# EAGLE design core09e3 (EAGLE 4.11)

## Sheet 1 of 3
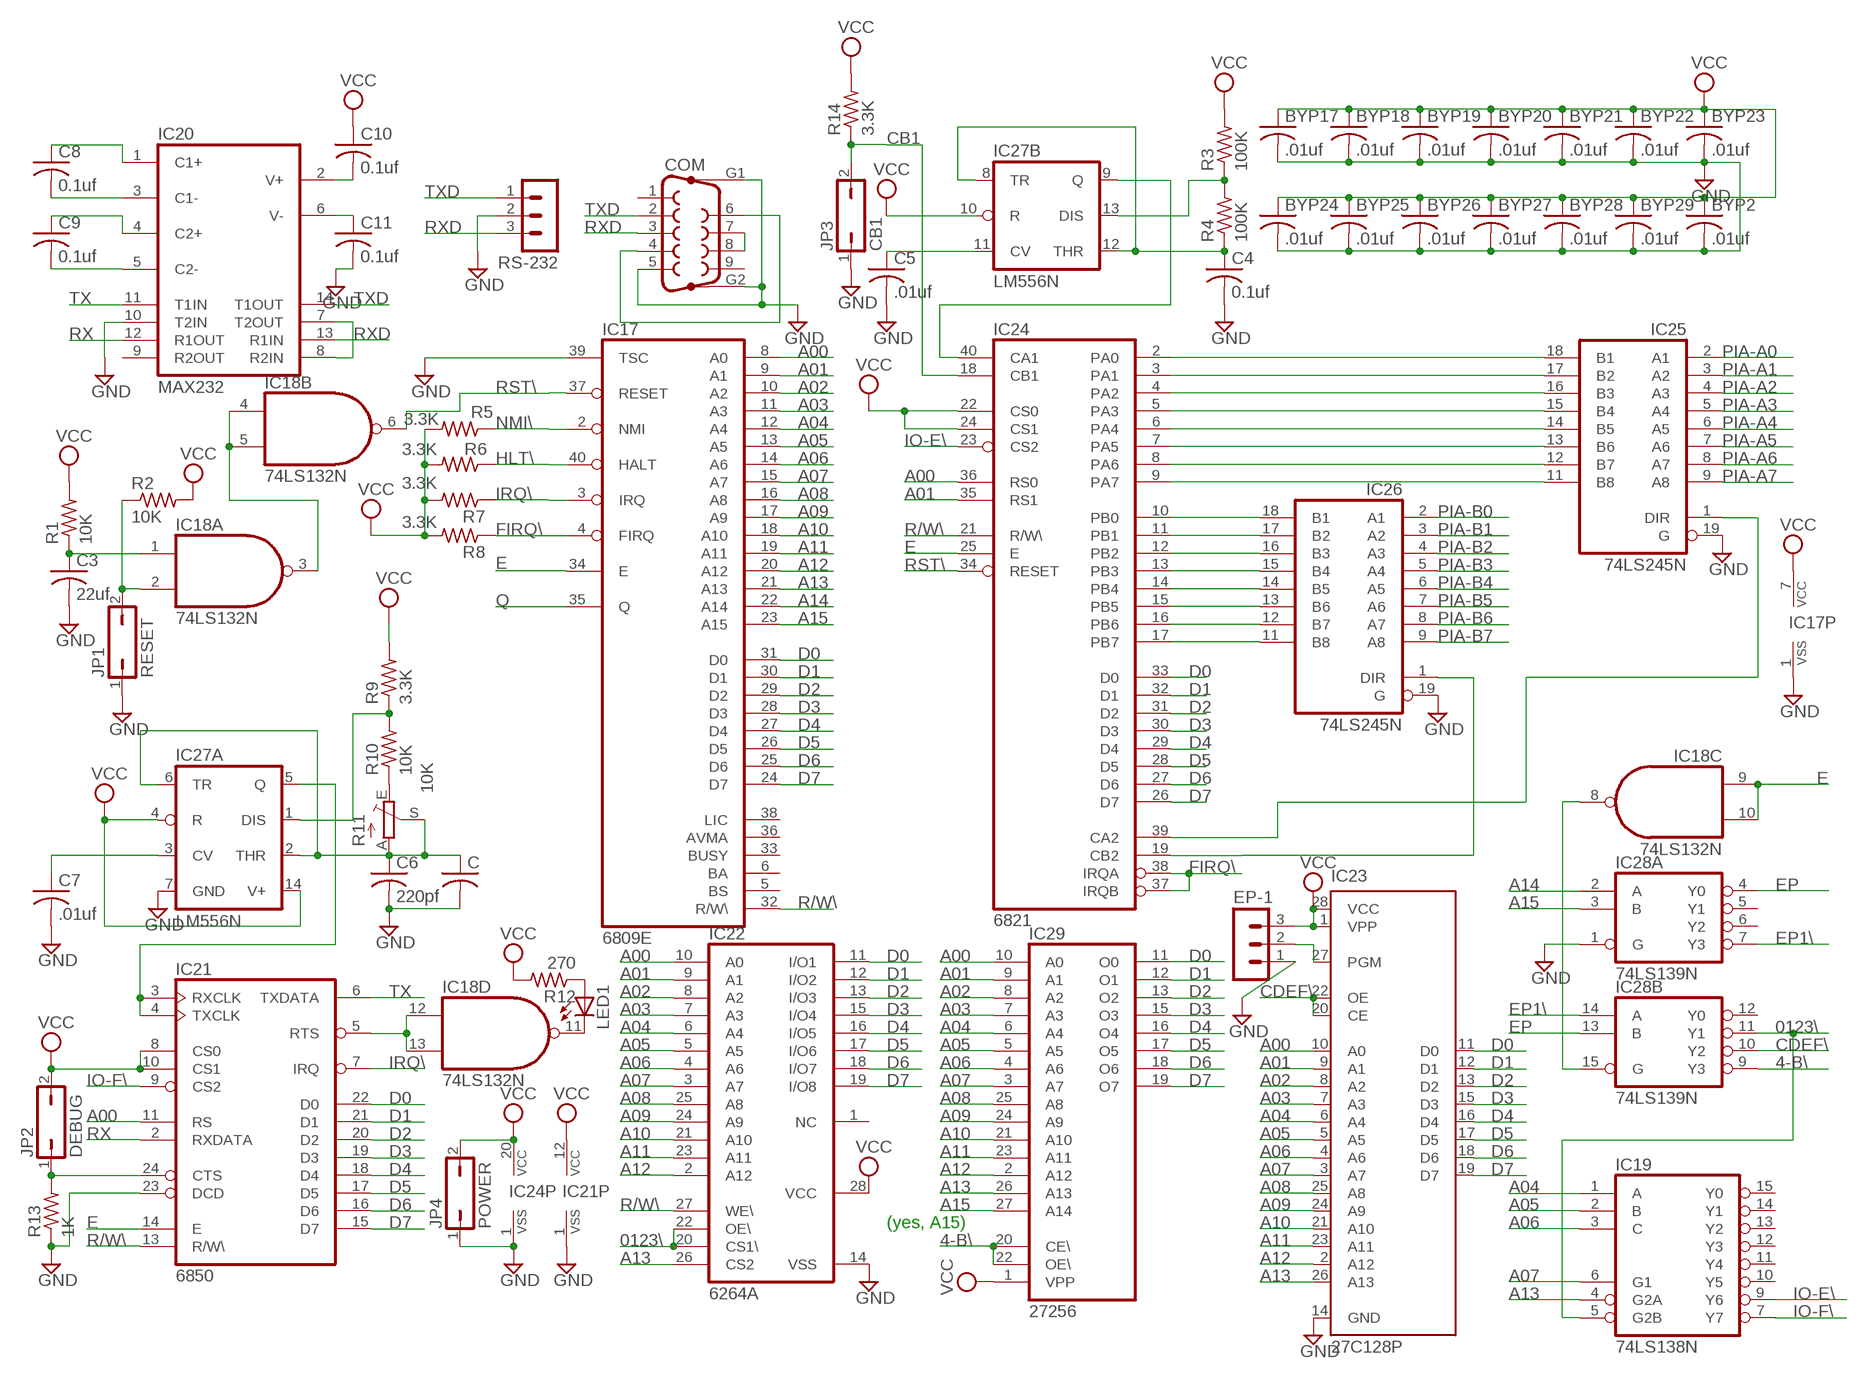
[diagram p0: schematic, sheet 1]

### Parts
BYP2  .01uf  C-US050-025X075  [C050-025X075]
BYP17  .01uf  C-US050-025X075  [C050-025X075]
BYP18  .01uf  C-US050-025X075  [C050-025X075]
BYP19  .01uf  C-US050-025X075  [C050-025X075]
BYP20  .01uf  C-US050-025X075  [C050-025X075]
BYP21  .01uf  C-US050-025X075  [C050-025X075]
BYP22  .01uf  C-US050-025X075  [C050-025X075]
BYP23  .01uf  C-US050-025X075  [C050-025X075]
BYP24  .01uf  C-US050-025X075  [C050-025X075]
BYP25  .01uf  C-US050-025X075  [C050-025X075]
BYP26  .01uf  C-US050-025X075  [C050-025X075]
BYP27  .01uf  C-US050-025X075  [C050-025X075]
BYP28  .01uf  C-US050-025X075  [C050-025X075]
BYP29  .01uf  C-US050-025X075  [C050-025X075]
C  C-US050-025X075  [C050-025X075]
C3  22uf  C-US102-054X133  [C102-054X133]
C4  0.1uf  C-US050-025X075  [C050-025X075]
C5  .01uf  C-US050-025X075  [C050-025X075]
C6  220pf  C-US050-025X075  [C050-025X075]
C7  .01uf  C-US050-025X075  [C050-025X075]
C8  0.1uf  C-US050-025X075  [C050-025X075]
C9  0.1uf  C-US050-025X075  [C050-025X075]
C10  0.1uf  C-US050-025X075  [C050-025X075]
C11  0.1uf  C-US050-025X075  [C050-025X075]
COM  F09HP  [F09HP]
EP-1  MA03-1  [MA03-1]
IC17  6809E  [DIL40]
IC18  74LS132N  74LS00N  [DIL14]
IC19  74LS138N  [DIL16]
IC20  MAX232  [DIL16]
IC21  6850  [DIL24]
IC22  6264A  [DIL28-6]
IC23  27C128P  [DIL28-6]
IC24  6821  [DIL40]
IC25  74LS245N  [DIL20]
IC26  74LS245N  [DIL20]
IC27  LM556N  [DIL14]
IC28  74LS139N  [DIL16]
IC29  27256  [DIL28]
JP1  RESET  JP1Q  [JP1]
JP2  DEBUG  JP1Q  [JP1]
JP3  CB1  JP1Q  [JP1]
JP4  POWER  JP1Q  [JP1]
LED1  LED3MM  [LED3MM]
R1  10K  R-US_0207/7  [0207/7]
R2  10K  R-US_0207/7  [0207/7]
R3  100K  R-US_0207/7  [0207/7]
R4  100K  R-US_0207/7  [0207/7]
R5  3.3K  R-US_0207/7  [0207/7]
R6  3.3K  R-US_0207/7  [0207/7]
R7  3.3K  R-US_0207/7  [0207/7]
R8  3.3K  R-US_0207/7  [0207/7]
R9  3.3K  R-US_0207/7  [0207/7]
R10  10K  R-US_0207/7  [0207/7]
R11  10K  TRIM_EU-B90P  [SP19L]
R12  270  R-US_0207/7  [0207/7]
R13  1K  R-US_0207/7  [0207/7]
R14  3.3K  R-US_0207/7  [0207/7]
RS-232  MA03-1  [MA03-1]

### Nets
4-B\: IC28.9(B:Y3) IC29.20(CE\) IC29.22(OE\)
0123\: IC19.5(G2B) IC22.20(CS1\) IC22.22(OE\) IC28.11(B:Y1)
A00: IC17.8(A0) IC21.11(RS) IC22.10(A0) IC23.10(A0) IC24.36(RS0) IC29.10(A0)
A01: IC17.9(A1) IC22.9(A1) IC23.9(A1) IC24.35(RS1) IC29.9(A1)
A02: IC17.10(A2) IC22.8(A2) IC23.8(A2) IC29.8(A2)
A03: IC17.11(A3) IC22.7(A3) IC23.7(A3) IC29.7(A3)
A04: IC17.12(A4) IC19.1(A) IC22.6(A4) IC23.6(A4) IC29.6(A4)
A05: IC17.13(A5) IC19.2(B) IC22.5(A5) IC23.5(A5) IC29.5(A5)
A06: IC17.14(A6) IC19.3(C) IC22.4(A6) IC23.4(A6) IC29.4(A6)
A07: IC17.15(A7) IC19.6(G1) IC22.3(A7) IC23.3(A7) IC29.3(A7)
A08: IC17.16(A8) IC22.25(A8) IC23.25(A8) IC29.25(A8)
A09: IC17.17(A9) IC22.24(A9) IC23.24(A9) IC29.24(A9)
A10: IC17.18(A10) IC22.21(A10) IC23.21(A10) IC29.21(A10)
A11: IC17.19(A11) IC22.23(A11) IC23.23(A11) IC29.23(A11)
A12: IC17.20(A12) IC22.2(A12) IC23.2(A12) IC29.2(A12)
A13: IC17.21(A13) IC19.4(G2A) IC22.26(CS2) IC23.26(A13) IC29.26(A13)
A14: IC17.22(A14) IC28.2(A:A)
A15: IC17.23(A15) IC28.3(A:B) IC29.27(A14)
CB1: IC24.18(CB1) JP3.2 R14.1
CDEF\: IC23.20(CE) IC23.22(OE) IC28.10(B:Y2)
D0: IC17.31(D0) IC21.22(D0) IC22.11(I/O1) IC23.11(D0) IC24.33(D0) IC29.11(O0)
D1: IC17.30(D1) IC21.21(D1) IC22.12(I/O2) IC23.12(D1) IC24.32(D1) IC29.12(O1)
D2: IC17.29(D2) IC21.20(D2) IC22.13(I/O3) IC23.13(D2) IC24.31(D2) IC29.13(O2)
D3: IC17.28(D3) IC21.19(D3) IC22.15(I/O4) IC23.15(D3) IC24.30(D3) IC29.15(O3)
D4: IC17.27(D4) IC21.18(D4) IC22.16(I/O5) IC23.16(D4) IC24.29(D4) IC29.16(O4)
D5: IC17.26(D5) IC21.17(D5) IC22.17(I/O6) IC23.17(D5) IC24.28(D5) IC29.17(O5)
D6: IC17.25(D6) IC21.16(D6) IC22.18(I/O7) IC23.18(D6) IC24.27(D6) IC29.18(O6)
D7: IC17.24(D7) IC21.15(D7) IC22.19(I/O8) IC23.19(D7) IC24.26(D7) IC29.19(O7)
E: IC17.34(E) IC18.9(C:I0) IC18.10(C:I1) IC21.14(E) IC24.25(E) ; also sheet 3
EP: IC28.4(A:Y0) IC28.13(B:B)
EP1\: IC28.7(A:Y3) IC28.14(B:A)
FIRQ\: IC17.4(FIRQ) IC24.37(IRQB) IC24.38(IRQA) R8.1
GND [Power]: BYP2.2 BYP17.2 BYP18.2 BYP19.2 BYP20.2 BYP21.2 BYP22.2 BYP23.2 BYP24.2 BYP25.2 BYP26.2 BYP27.2 BYP28.2 BYP29.2 C3.2 C4.2 C5.2 C6.2 C7.2 C11.2 C.2 COM.5 COM.G1 COM.G2 EP-1.1 IC17.1(VSS) IC17.39(TSC) IC20.10(T2IN) IC21.1(VSS) IC21.23(DCD) IC22.14(VSS) IC23.14(GND) IC24.1(VSS) IC25.19(G) IC26.19(G) IC27.7(A:GND) IC28.1(A:G) JP1.1 JP3.1 JP4.1 R13.1 RS-232.2 ; also sheet 2,3
HLT\: IC17.40(HALT) R5.1
IO-E\: IC19.9(Y6) IC24.23(CS2)
IO-F\: IC19.7(Y7) IC21.9(CS2)
IRQ\: IC17.3(IRQ) IC21.7(IRQ) R7.1
N$1: COM.4 COM.6
N$4: EP-1.2 IC23.27(PGM)
N$5: IC24.2(PA0) IC25.18(B1)
N$6: IC18.3(A:O) IC18.4(B:I0) IC18.5(B:I1)
N$21: C3.1 IC18.1(A:I0) R1.1
N$22: IC18.2(A:I1) JP1.2 R2.1
N$23: IC21.3(RXCLK) IC21.4(TXCLK) IC27.5(A:Q)
N$24: IC24.10(PB0) IC26.18(B1)
N$25: IC24.11(PB1) IC26.17(B2)
N$27: C6.1 C.1 IC27.2(A:THR) IC27.6(A:TR) R11.A R11.S
N$28: IC27.1(A:DIS) R9.1 R10.2
N$94: IC24.12(PB2) IC26.16(B3)
N$124: IC24.13(PB3) IC26.15(B4)
N$125: IC24.14(PB4) IC26.14(B5)
N$126: IC24.15(PB5) IC26.13(B6)
N$127: IC24.16(PB6) IC26.12(B7)
N$128: IC24.17(PB7) IC26.11(B8)
N$129: IC24.3(PA1) IC25.17(B2)
N$130: IC24.4(PA2) IC25.16(B3)
N$131: IC24.5(PA3) IC25.15(B4)
N$132: IC24.6(PA4) IC25.14(B5)
N$133: IC24.7(PA5) IC25.13(B6)
N$134: IC24.8(PA6) IC25.12(B7)
N$135: IC24.9(PA7) IC25.11(B8)
N$136: IC24.19(CB2) IC26.1(DIR)
N$137: IC24.39(CA2) IC25.1(DIR)
N$138: IC24.40(CA1) IC27.9(B:Q)
N$140: C4.1 IC27.8(B:TR) IC27.12(B:THR) R4.1
N$141: IC27.13(B:DIS) R3.1 R4.2
N$142: C5.1 IC27.11(B:CV)
N$143: R10.1 R11.E
N$145: COM.7 COM.8
N$147: IC18.12(D:I0) IC18.13(D:I1) IC21.5(RTS)
N$148: IC18.11(D:O) LED1.K(C)
N$149: LED1.A R12.1
N$150: IC21.24(CTS) JP2.1 R13.2
N$151: IC18.8(C:O) IC28.15(B:G)
N$153: IC20.7(T2OUT) IC20.8(R2IN)
N$154: C7.1 IC27.3(A:CV)
N$155: C9.2 IC20.5(C2-)
N$156: C9.1 IC20.4(C2+)
N$157: C8.2 IC20.3(C1-)
N$158: C8.1 IC20.1(C1+)
N$159: C11.1 IC20.6(V-)
N$160: C10.2 IC20.2(V+)
NMI\: IC17.2(NMI) R6.1
PIA-A0: IC25.2(A1) ; also sheet 2
PIA-A1: IC25.3(A2) ; also sheet 2
PIA-A2: IC25.4(A3) ; also sheet 2
PIA-A3: IC25.5(A4) ; also sheet 2
PIA-A4: IC25.6(A5) ; also sheet 2
PIA-A5: IC25.7(A6) ; also sheet 2
PIA-A6: IC25.8(A7) ; also sheet 2
PIA-A7: IC25.9(A8) ; also sheet 2
PIA-B0: IC26.2(A1) ; also sheet 2
PIA-B1: IC26.3(A2) ; also sheet 2
PIA-B2: IC26.4(A3) ; also sheet 2
PIA-B3: IC26.5(A4) ; also sheet 2
PIA-B4: IC26.6(A5) ; also sheet 2
PIA-B5: IC26.7(A6) ; also sheet 2
PIA-B6: IC26.8(A7) ; also sheet 2
PIA-B7: IC26.9(A8) ; also sheet 2
Q: IC17.35(Q) ; also sheet 3
R/W\: IC17.32(R/W\) IC21.13(R/W\) IC22.27(WE\) IC24.21(R/W\)
RST\: IC17.37(RESET) IC18.6(B:O) IC24.34(RESET)
RX: IC20.12(R1OUT) IC21.2(RXDATA)
RXD: COM.3 IC20.13(R1IN) RS-232.3
TX: IC20.11(T1IN) IC21.6(TXDATA)
TXD: COM.2 IC20.14(T1OUT) RS-232.1
VCC [Power]: BYP2.1 BYP17.1 BYP18.1 BYP19.1 BYP20.1 BYP21.1 BYP22.1 BYP23.1 BYP24.1 BYP25.1 BYP26.1 BYP27.1 BYP28.1 BYP29.1 C10.1 EP-1.3 IC17.7(VCC) IC21.8(CS0) IC21.10(CS1) IC21.12(VCC) IC22.28(VCC) IC23.1(VPP) IC23.28(VCC) IC24.20(VCC) IC24.22(CS0) IC24.24(CS1) IC27.4(A:R) IC27.10(B:R) IC27.14(A:V+) IC29.1(VPP) JP2.2 JP4.2 R1.2 R2.2 R3.2 R5.2 R6.2 R7.2 R8.2 R9.2 R12.2 R14.2 ; also sheet 2,3
Unconnected: COM.1 COM.9 IC17.5(BS) IC17.6(BA) IC17.33(BUSY) IC17.36(AVMA) IC17.38(LIC) IC19.10(Y5) IC19.11(Y4) IC19.12(Y3) IC19.13(Y2) IC19.14(Y1) IC19.15(Y0) IC20.9(R2OUT) IC22.1(NC) IC28.5(A:Y1) IC28.6(A:Y2) IC28.12(B:Y0)

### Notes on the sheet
- (yes, A15)

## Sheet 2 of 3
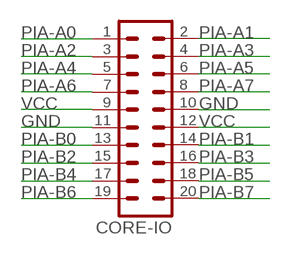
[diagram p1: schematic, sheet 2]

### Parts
CORE-IO  MA10-2  [MA10-2]

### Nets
GND [Power]: CORE-IO.10 CORE-IO.11 ; also sheet 1,3
PIA-A0: CORE-IO.1 ; also sheet 1
PIA-A1: CORE-IO.2 ; also sheet 1
PIA-A2: CORE-IO.3 ; also sheet 1
PIA-A3: CORE-IO.4 ; also sheet 1
PIA-A4: CORE-IO.5 ; also sheet 1
PIA-A5: CORE-IO.6 ; also sheet 1
PIA-A6: CORE-IO.7 ; also sheet 1
PIA-A7: CORE-IO.8 ; also sheet 1
PIA-B0: CORE-IO.13 ; also sheet 1
PIA-B1: CORE-IO.14 ; also sheet 1
PIA-B2: CORE-IO.15 ; also sheet 1
PIA-B3: CORE-IO.16 ; also sheet 1
PIA-B4: CORE-IO.17 ; also sheet 1
PIA-B5: CORE-IO.18 ; also sheet 1
PIA-B6: CORE-IO.19 ; also sheet 1
PIA-B7: CORE-IO.20 ; also sheet 1
VCC [Power]: CORE-IO.9 CORE-IO.12 ; also sheet 1,3

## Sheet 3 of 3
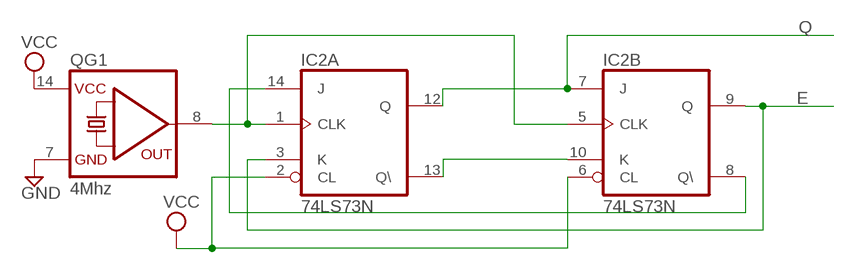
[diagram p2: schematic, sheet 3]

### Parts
IC2  74LS73N  [DIL14]
QG1  4Mhz  QG5860  [DIL14S]

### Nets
E: IC2.3(A:K) IC2.9(B:Q) ; also sheet 1
GND [Power]: QG1.7(GND) ; also sheet 1,2
N$2: IC2.1(A:CLK) IC2.5(B:CLK) QG1.8(OUT)
N$3: IC2.10(B:K) IC2.13(A:Q\)
N$7: IC2.8(B:Q\) IC2.14(A:J)
Q: IC2.7(B:J) IC2.12(A:Q) ; also sheet 1
VCC [Power]: IC2.2(A:CL) IC2.6(B:CL) QG1.14(VCC) ; also sheet 1,2

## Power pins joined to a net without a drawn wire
GND: IC2.11(P:GND) IC18.7(P:GND) IC19.8(GND) IC20.15(GND) IC25.10(GND) IC26.10(GND) IC28.8(P:GND) IC29.14(GND)
VCC: IC2.4(P:VCC) IC18.14(P:VCC) IC19.16(VCC) IC20.16(VCC) IC25.20(VCC) IC26.20(VCC) IC28.16(P:VCC) IC29.28(VCC)

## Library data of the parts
BYP2 BYP17-BYP29 C C3-C11 = rcl:C-US: CAPACITOR, American symbol
COM = con-subd:F09HP: SUB-D
CORE-IO = con-lstb:MA10-2: PIN HEADER
EP-1 RS-232 = con-lstb:MA03-1: PIN HEADER
IC2 = 74xx-us:74*73: Dual J-K FLIP FLOP, clear
IC17 = micro-motorola:6809E: MICROCONTROLLER/MEMORY DEVICE
IC18 = 74xx-us:74*00: Quad 2-input NAND gate
IC19 = 74xx-us:74*138: 3-line to 8-line DECODER/DEMULTIPLEXER
IC20 = maxim:MAX232: RS232 TRANSEIVER
IC21 = micro-motorola:6850: MICROCONTROLLER/MEMORY DEVICE
IC22 = memory-hitachi:6264A: MEMORY
IC23 = microchip:27*128: CMOS EPROM 128 K (16 K x 8)
IC24 = micro-motorola:6821: MICROCONTROLLER/MEMORY DEVICE
IC25 IC26 = 74xx-us:74*245: Octal BUS TRANSCEIVER, 3-state
IC27 = linear:*556: Dual TIMER
IC28 = 74xx-us:74*139: Dual 2-line to 4-line DECODER/DEMULTIPLEXER
IC29 = memory:27256: MEMORY
JP1-JP4 = jumper:JP1Q: JUMPER
LED1 = led:LED: LED
QG1 = crystal:QG5860: CRYSTAL RESONATOR
R1-R10 R12-R14 = rcl:R-US_: RESISTOR, American symbol
R11 = pot:TRIM_EU-: POTENTIOMETER

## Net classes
1 Power: width 0.508 mm, drill 0.254 mm, clearance 0.254 mm

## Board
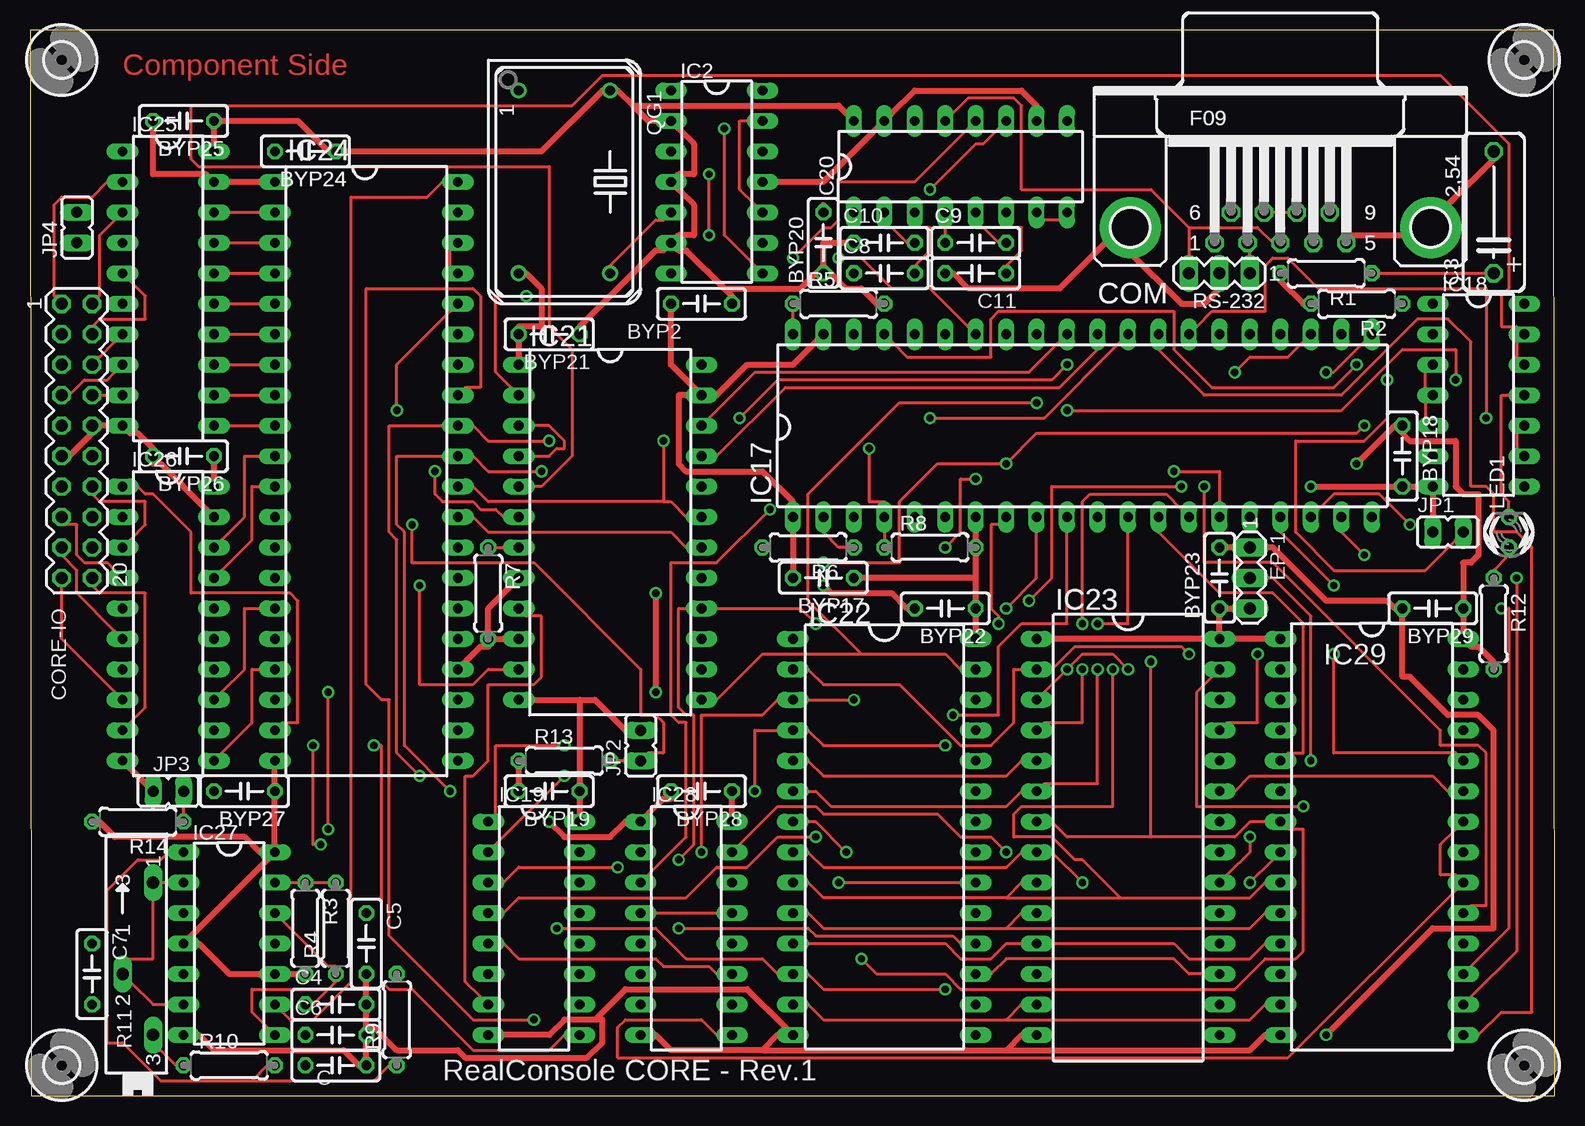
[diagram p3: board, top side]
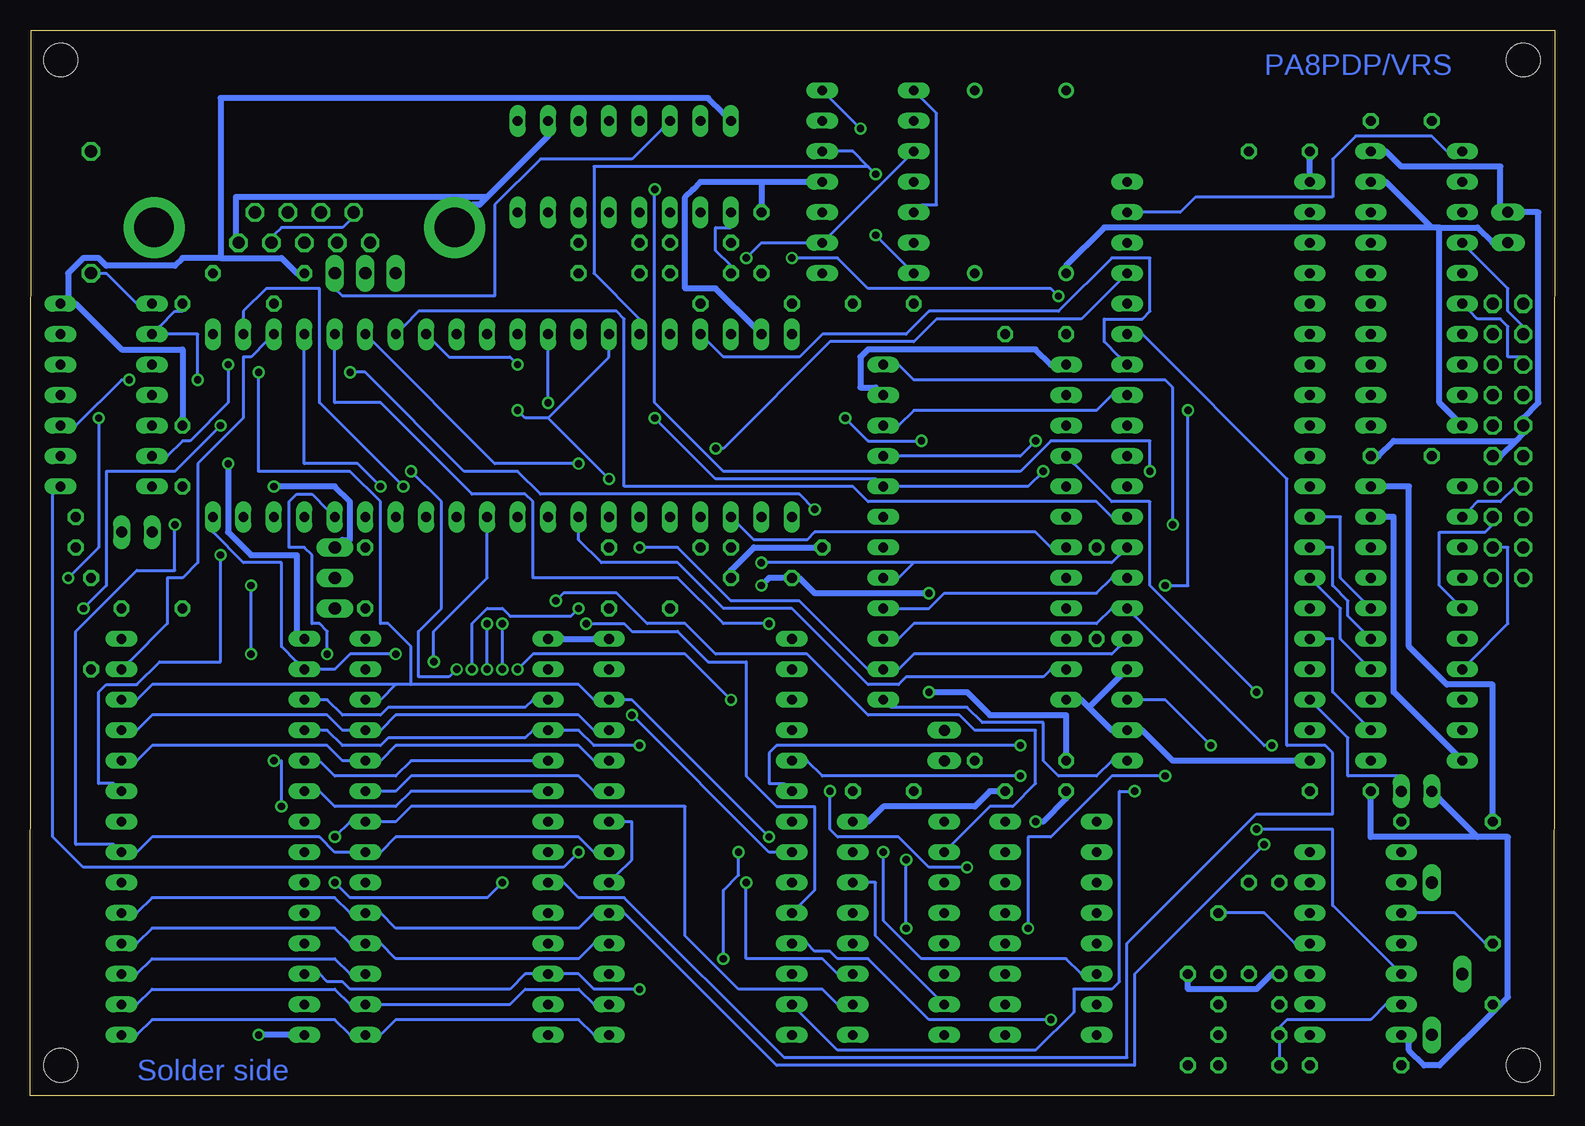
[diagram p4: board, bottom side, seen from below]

Size 127.11 x 88.87 mm. Coordinates in mm from the lower left corner, seen from the top.
Outline: 0.1,0 127.11,0 127.01,88.87 0,88.87 0.1,0
Copper layers (1*16): Top 0.035mm / dielectric 1.5mm / Bottom 0.035mm
Design rules "olimex10mil": minimum track width 10mil, minimum drill 24mil, track to track 10mil, track to pad 10mil, pad to pad 10mil, via to via 10mil, smd to smd 10mil, copper to edge 40mil, drill to drill 10mil, minimum pad ring 10mil, minimum via ring 8mil, stop-mask expansion 0mil, vias tented up to drill 0mil, thermal gap 10mil

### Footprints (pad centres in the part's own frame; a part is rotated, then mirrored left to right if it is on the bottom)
C050-025X075 = drill 0.813 octagon: 1 -2.54,0; 2 2.54,0
C102-054X133 = drill 1.016 octagon: 1 -5.08,0; 2 5.08,0
F09HP = drill 1.016 octagon: 1 -5.486,-1.27; 2 -2.743,-1.27; 3 0,-1.27; 4 2.743,-1.27; 5 5.486,-1.27; 6 -4.115,1.27; 7 -1.372,1.27; 8 1.372,1.27; 9 4.115,1.27 | drill 3.302 pad 5.08 round: G1 -12.522,0; G2 12.522,0
MA10-2 = drill 1.016 octagon: 1 -11.43,-1.27; 2 -11.43,1.27; 3 -8.89,-1.27; 4 -8.89,1.27; 5 -6.35,-1.27; 6 -6.35,1.27; 7 -3.81,-1.27; 8 -3.81,1.27; 9 -1.27,-1.27; 10 -1.27,1.27; 11 1.27,-1.27; 12 1.27,1.27; 13 3.81,-1.27; 14 3.81,1.27; 15 6.35,-1.27; 16 6.35,1.27; 17 8.89,-1.27; 18 8.89,1.27; 19 11.43,-1.27; 20 11.43,1.27
MA03-1 = drill 1.016 long: 1 -2.54,0; 2 0,0; 3 2.54,0
DIL14 = drill 0.813 long: 1 -7.62,-3.81; 2 -5.08,-3.81; 3 -2.54,-3.81; 4 0,-3.81; 5 2.54,-3.81; 6 5.08,-3.81; 7 7.62,-3.81; 8 7.62,3.81; 9 5.08,3.81; 10 2.54,3.81; 11 0,3.81; 12 -2.54,3.81; 13 -5.08,3.81; 14 -7.62,3.81
DIL40 = drill 0.813 long: 1 -24.13,-7.62; 2 -21.59,-7.62; 3 -19.05,-7.62; 4 -16.51,-7.62; 5 -13.97,-7.62; 6 -11.43,-7.62; 7 -8.89,-7.62; 8 -6.35,-7.62; 9 -3.81,-7.62; 10 -1.27,-7.62; 11 1.27,-7.62; 12 3.81,-7.62; 13 6.35,-7.62; 14 8.89,-7.62; 15 11.43,-7.62; 16 13.97,-7.62; 17 16.51,-7.62; 18 19.05,-7.62; 19 21.59,-7.62; 20 24.13,-7.62; 21 24.13,7.62; 22 21.59,7.62; 23 19.05,7.62; 24 16.51,7.62; 25 13.97,7.62; 26 11.43,7.62; 27 8.89,7.62; 28 6.35,7.62; 29 3.81,7.62; 30 1.27,7.62; 31 -1.27,7.62; 32 -3.81,7.62; 33 -6.35,7.62; 34 -8.89,7.62; 35 -11.43,7.62; 36 -13.97,7.62; 37 -16.51,7.62; 38 -19.05,7.62; 39 -21.59,7.62; 40 -24.13,7.62
DIL16 = drill 0.813 long: 1 -8.89,-3.81; 2 -6.35,-3.81; 3 -3.81,-3.81; 4 -1.27,-3.81; 5 1.27,-3.81; 6 3.81,-3.81; 7 6.35,-3.81; 8 8.89,-3.81; 9 8.89,3.81; 10 6.35,3.81; 11 3.81,3.81; 12 1.27,3.81; 13 -1.27,3.81; 14 -3.81,3.81; 15 -6.35,3.81; 16 -8.89,3.81
DIL24 = drill 0.813 long: 1 -13.97,-7.62; 2 -11.43,-7.62; 3 -8.89,-7.62; 4 -6.35,-7.62; 5 -3.81,-7.62; 6 -1.27,-7.62; 7 1.27,-7.62; 8 3.81,-7.62; 9 6.35,-7.62; 10 8.89,-7.62; 11 11.43,-7.62; 12 13.97,-7.62; 13 13.97,7.62; 14 11.43,7.62; 15 8.89,7.62; 16 6.35,7.62; 17 3.81,7.62; 18 1.27,7.62; 19 -1.27,7.62; 20 -3.81,7.62; 21 -6.35,7.62; 22 -8.89,7.62; 23 -11.43,7.62; 24 -13.97,7.62
DIL28-6 = drill 0.813 long: 1 -16.51,-7.62; 2 -13.97,-7.62; 3 -11.43,-7.62; 4 -8.89,-7.62; 5 -6.35,-7.62; 6 -3.81,-7.62; 7 -1.27,-7.62; 8 1.27,-7.62; 9 3.81,-7.62; 10 6.35,-7.62; 11 8.89,-7.62; 12 11.43,-7.62; 13 13.97,-7.62; 14 16.51,-7.62; 15 16.51,7.62; 16 13.97,7.62; 17 11.43,7.62; 18 8.89,7.62; 19 6.35,7.62; 20 3.81,7.62; 21 1.27,7.62; 22 -1.27,7.62; 23 -3.81,7.62; 24 -6.35,7.62; 25 -8.89,7.62; 26 -11.43,7.62; 27 -13.97,7.62; 28 -16.51,7.62
DIL20 = drill 0.813 long: 1 -11.43,-3.81; 2 -8.89,-3.81; 3 -6.35,-3.81; 4 -3.81,-3.81; 5 -1.27,-3.81; 6 1.27,-3.81; 7 3.81,-3.81; 8 6.35,-3.81; 9 8.89,-3.81; 10 11.43,-3.81; 11 11.43,3.81; 12 8.89,3.81; 13 6.35,3.81; 14 3.81,3.81; 15 1.27,3.81; 16 -1.27,3.81; 17 -3.81,3.81; 18 -6.35,3.81; 19 -8.89,3.81; 20 -11.43,3.81
DIL28 = drill 0.813 long: 1 -16.51,-7.62; 2 -13.97,-7.62; 3 -11.43,-7.62; 4 -8.89,-7.62; 5 -6.35,-7.62; 6 -3.81,-7.62; 7 -1.27,-7.62; 8 1.27,-7.62; 9 3.81,-7.62; 10 6.35,-7.62; 11 8.89,-7.62; 12 11.43,-7.62; 13 13.97,-7.62; 14 16.51,-7.62; 15 16.51,7.62; 16 13.97,7.62; 17 11.43,7.62; 18 8.89,7.62; 19 6.35,7.62; 20 3.81,7.62; 21 1.27,7.62; 22 -1.27,7.62; 23 -3.81,7.62; 24 -6.35,7.62; 25 -8.89,7.62; 26 -11.43,7.62; 27 -13.97,7.62; 28 -16.51,7.62
JP1 = drill 0.914 long: 1 0,-1.27; 2 0,1.27
LED3MM = drill 0.813 octagon: A -1.27,0; K 1.27,0
DIL14S = drill 0.813 round: 1 -7.62,-3.81; 7 7.62,-3.81; 8 7.62,3.81; 14 -7.62,3.81
0207/7 = drill 0.813 octagon: 1 -3.81,0; 2 3.81,0
SP19L = drill 1.016 long: A 5.715,-1.27; E -6.985,-1.27; S -1.905,1.27
2,8 = hole 2.8: 0,0

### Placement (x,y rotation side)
BYP2  55.98,66.05 180 top
BYP17  66.14,43.19 180 top
BYP18  114.4,53.35 270 top
BYP19  43.28,25.41 180 top
BYP20  66.14,71.13 90 top
BYP21  43.28,63.51 180 top
BYP22  76.3,40.65 180 top
BYP23  99.16,43.19 90 top
BYP24  22.96,78.75 180 top
BYP25  12.8,81.29 180 top
BYP26  12.8,53.35 180 top
BYP27  17.88,25.41 180 top
BYP28  55.98,25.41 180 top
BYP29  116.94,40.65 180 top
C  25.5,2.55 0 top
C3  122.02,73.67 90 top
C4  25.5,7.63 0 top
C5  28.04,12.71 270 top
C6  25.5,5.09 0 top
C7  5.18,10.17 270 top
C8  71.22,68.59 0 top
C9  78.84,71.13 0 top
C10  71.22,71.13 0 top
C11  78.84,68.59 180 top
COM  104.24,72.4 0 top
CORE-IO  3.91,54.62 270 top
EP-1  101.7,43.19 270 top
IC2  57.25,76.21 270 top
IC17  87.73,55.89 0 top
IC18  120.75,58.43 270 top
IC19  42.01,13.98 270 top
IC20  77.57,77.48 0 top
IC21  48.36,47 270 top
IC22  71.22,21.6 270 top
IC23  91.54,21.6 270 top
IC24  28.04,52.08 270 top
IC25  11.53,67.32 270 top
IC26  11.53,39.38 270 top
IC27  16.61,12.71 270 top
IC28  54.71,13.98 270 top
IC29  111.86,21.6 270 top
JP1  118.21,47 270 top
JP2  50.9,29.22 0 top
JP3  11.53,25.41 270 top
JP4  3.91,72.4 0 top
LED1  123.29,47 90 top
QG1  44.55,76.21 270 top
R1  108.05,68.59 180 top
R2  110.59,66.05 180 top
R3  22.96,13.98 270 top
R4  25.5,13.98 90 top
R5  67.41,66.05 0 top
R6  64.87,45.73 180 top
R7  38.2,41.92 270 top
R8  75.03,45.73 0 top
R9  30.58,6.36 90 top
R10  16.61,2.55 0 top
R11  8.99,12.08 90 top
R12  122.02,39.38 270 top
R13  44.55,27.95 0 top
R14  8.99,22.87 180 top
RS-232  99.16,68.59 180 top
U$3  [2,8]  2.64,86.37 0 top
U$4  [2,8]  2.64,2.55 0 top
U$5  [2,8]  124.56,86.37 0 top
U$6  [2,8]  124.56,2.55 0 top

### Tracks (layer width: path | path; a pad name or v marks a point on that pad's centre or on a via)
4-B\
  Top 0.254: IC28.9 57.25,5.09 55.98,6.36 49.63,6.36 48.99,5.73 48.99,3.19 104.87,3.19 118.84,17.16 IC29.20 118.84,18.43 117.57,18.43 117.57,20.97 118.84,22.24 IC29.22
0123\  (via drill 0.61)
  Top 0.254: IC28.11 57.25,10.17 56.61,10.81 52.8,10.81 52.17,11.44 40.74,11.44 39.47,12.71 IC19.5 | v67.41,17.79 77.57,17.79 IC22.20
  Bottom 0.254: IC22.20 78.2,18.43 76.93,19.7 76.93,22.87 77.57,22.87 IC22.22 | v67.41,17.79 67.41,11.44 61.06,11.44 59.79,10.17 IC28.11
A00  (via drill 0.61)
  Top 0.254: 81.38,13.98 66.14,13.98 64.87,15.25 IC22.10 | 81.38,13.98 82.65,15.25 IC23.10 | 81.38,13.98 101.7,13.98 102.97,15.25 IC29.10 | v30.58,57.16 30.58,60.97 35.02,65.42 IC24.36 | v32.48,42.56 32.48,34.3 36.93,34.3 38.2,35.57 39.47,35.57 IC21.11 | v80.74,39.38 80.74,40.02 80.11,40.65 80.11,47.64 80.74,47.64 IC17.8
  Bottom 0.254: IC21.11 42.01,35.57 42.64,34.94 54.07,34.94 54.71,34.3 57.25,34.3 63.6,40.65 69.31,40.65 73.12,44.46 79.47,44.46 81.38,46.37 81.38,47 IC17.8 | v30.58,57.16 30.58,42.56 v32.48,42.56 | v80.74,39.38 77.57,39.38 76.93,38.75 73.12,38.75 70.58,36.21 67.41,36.21 67.41,26.68 64.87,24.14 61.69,24.14 61.69,17.16 62.96,15.89 IC22.10
A01  (via drill 0.61)
  Top 0.254: 81.38,16.52 66.14,16.52 64.87,17.79 IC22.9 | 81.38,16.52 82.65,17.79 IC23.9 | 81.38,16.52 90.9,16.52 | 90.9,16.52 101.7,16.52 102.97,17.79 IC29.9 | v81.38,40.65 83.92,43.19 83.92,47 IC17.9 | v90.27,35.57 90.27,24.14 82.65,24.14 82.01,23.51 82.01,21.6 85.19,21.6 87.09,19.7 87.73,19.7 90.9,16.52
  Bottom 0.254: v81.38,40.65 82.01,40.02 87.09,40.02 87.73,40.65 89,40.65 90.27,39.38 v90.27,35.57 | IC24.35 34.39,63.51 22.32,51.45 22.32,29.22 19.15,29.22 18.51,28.59 18.51,23.51 24.86,23.51 35.66,12.71 35.66,3.19 64.23,3.19 77.57,16.52 81.38,16.52 82.65,17.79 IC23.9
A02  (via drill 0.61)
  Top 0.254: IC22.8 64.87,20.33 66.14,19.06 81.38,19.06 82.65,20.33 IC23.8 85.19,20.33 v87.73,17.79 | v101.7,17.79 103.6,19.7 IC29.8 | v76.93,31.76 80.74,31.76 80.74,37.48 82.65,39.38 86.46,39.38 86.46,47 IC17.10
  Bottom 0.254: v101.7,17.79 100.43,16.52 89,16.52 v87.73,17.79 | v76.93,31.76 65.5,20.33 64.87,20.33 IC22.8
A03  (via drill 0.61)
  Top 0.254: v68.04,20.33 65.5,22.87 64.87,22.87 IC22.7 | v69.31,11.44 70.58,10.17 76.3,10.17 77.57,8.9 100.43,8.9 102.97,11.44 105.51,11.44 106.14,12.08 106.14,22.24 104.87,22.24 IC29.7 102.97,22.87 101.7,22.87 100.43,21.6 93.44,21.6 | 93.44,21.6 86.46,21.6 85.19,22.87 IC23.7 | 93.44,21.6 v93.44,36.21
  Bottom 0.254: v68.04,20.33 68.04,18.43 69.31,17.16 v69.31,11.44 | v93.44,36.21 93.44,38.75 89,43.19 89,47 IC17.11
A04  (via drill 0.61)
  Top 0.254: v44.55,29.22 38.83,29.22 38.83,23.51 IC19.1 | IC22.6 64.87,25.41 65.5,25.41 66.77,24.14 81.38,24.14 82.65,25.41 IC23.6 84.55,26.05 89,26.05 v89,35.57 | v89,39.38 91.54,39.38 91.54,47 IC17.12
  Bottom 0.254: v44.55,29.22 64.87,29.22 65.5,28.59 65.5,26.05 64.23,26.05 IC22.6 | v89,35.57 v89,39.38 | IC29.6 102.97,25.41 101.7,24.14 96.62,24.14 95.35,25.41 85.19,25.41 IC23.6
A05  (via drill 0.61)
  Top 0.254: v44.55,26.68 38.83,20.97 IC19.2 | IC23.5 82.65,27.95 81.38,26.68 66.14,26.68 64.87,27.95 IC22.5 | IC17.13 94.08,47 99.16,41.92 103.6,41.92 106.14,39.38 106.14,28.59 104.87,28.59 IC29.5
  Bottom 0.254: v44.55,26.68 61.06,26.68 62.33,27.95 IC22.5 | IC29.5 102.97,27.95 101.7,26.68 96.62,26.68 95.35,27.95 85.19,27.95 IC23.5
A06  (via drill 0.61)
  Top 0.254: v48.99,19.06 40.74,19.06 39.47,17.79 IC19.3 | v60.42,25.41 60.42,30.49 62.33,30.49 IC22.4 64.87,30.49 66.14,29.22 v76.3,29.22 | v87.73,39.38 87.73,49.54 88.36,50.18 94.71,50.18 95.98,48.91 IC17.14 | v87.73,35.57 87.73,31.13 84.55,31.13 IC23.4
  Bottom 0.254: v48.99,19.06 52.17,19.06 54.71,21.6 59.79,21.6 60.42,22.24 v60.42,25.41 | IC29.4 102.97,30.49 102.33,30.49 101.06,29.22 97.89,29.22 97.25,29.86 85.82,29.86 85.19,30.49 IC23.4 82.65,30.49 81.38,30.49 80.11,29.22 v76.3,29.22 | v87.73,35.57 v87.73,39.38
A07  (via drill 0.61)
  Top 0.254: v55.98,20.33 55.98,31.76 61.06,31.76 62.33,33.03 IC22.3 64.87,33.03 v68.68,33.03 | IC23.3 84.55,33.67 v86.46,35.57 87.73,36.84 90.27,36.84 v91.54,35.57 | v95.35,52.08 99.16,52.08 99.16,49.54 IC17.15
  Bottom 0.254: IC23.3 85.19,33.03 85.82,32.4 97.25,32.4 97.89,31.76 101.06,31.76 102.33,33.03 102.97,33.03 IC29.3 | v55.98,20.33 55.98,14.62 52.8,11.44 40.74,11.44 39.47,10.17 IC19.6 | v86.46,35.57 85.19,36.84 72.49,36.84 v68.68,33.03 | v95.35,52.08 92.81,49.54 92.81,40.65 94.71,38.75 94.71,34.94 92.17,34.94 v91.54,35.57
A08  (via drill 0.61)
  Top 0.254: v102.33,36.84 102.33,31.13 99.79,31.13 IC23.25
  Bottom 0.254: IC22.25 80.11,30.49 81.38,31.76 96.62,31.76 97.89,30.49 IC23.25 100.43,30.49 101.06,30.49 102.33,31.76 116.94,31.76 118.21,30.49 IC29.25 | v102.33,36.84 102.33,38.75 102.97,39.38 103.6,39.38 103.6,45.1 104.24,45.73 105.51,45.73 105.51,49.54 104.87,50.18 103.6,50.18 102.33,48.91 IC17.16
A09  (via drill 0.61)
  Top 0.254: v108.68,42.56 104.24,47 IC17.17 | v108.68,36.84 108.68,28.59 118.84,28.59 IC29.24
  Bottom 0.254: IC22.24 80.11,27.95 81.38,29.22 96.62,29.22 97.89,27.95 IC23.24 100.43,27.95 101.06,27.95 102.33,29.22 116.94,29.22 118.21,27.95 IC29.24 | v108.68,36.84 v108.68,42.56
A10  (via drill 0.61)
  Top 0.254: v115.03,47.64 112.49,50.18 108.68,50.18 107.41,48.91 IC17.18
  Bottom 0.254: IC22.21 80.11,20.33 81.38,21.6 96.62,21.6 97.89,20.33 IC23.21 100.43,20.33 101.7,20.33 102.97,21.6 116.94,21.6 118.21,20.33 IC29.21 120.11,20.97 123.29,20.97 123.29,38.75 118.21,43.83 115.03,43.83 v115.03,47.64
A11  (via drill 0.61)
  Top 0.254: IC29.23 118.21,25.41 116.94,26.68 101.7,26.68 100.43,25.41 IC23.23 | v111.22,45.1 109.32,47 IC17.19
  Bottom 0.254: IC22.23 80.11,25.41 81.38,26.68 95.35,26.68 96.62,25.41 97.89,25.41 IC23.23 | v111.22,45.1 111.22,36.21 116.3,36.21 118.21,34.3 120.75,34.3 121.38,33.67 121.38,26.05 120.11,26.05 IC29.23
A12  (via drill 0.61)
  Top 0.254: IC22.2 64.87,35.57 66.14,34.3 72.49,34.3 77.57,29.22 80.11,29.22 82.01,31.13 82.01,35.57 82.65,35.57 IC23.2 85.19,35.57 87.09,37.48 95.98,37.48 v96.62,36.84
  Bottom 0.254: IC17.20 111.86,47 109.32,44.46 106.14,44.46 106.14,37.48 104.87,36.21 IC29.2 102.97,35.57 101.7,35.57 100.43,36.84 v96.62,36.84
A13  (via drill 0.61)
  Top 0.254: v65.5,21.6 62.33,21.6 59.79,19.06 57.25,19.06 54.71,16.52 40.74,16.52 39.47,15.25 IC19.4 | v108.05,60.34 108.68,60.34 111.22,62.88 IC17.21
  Bottom 0.254: v65.5,21.6 76.93,33.03 77.57,33.03 IC22.26 80.11,33.03 81.38,34.3 95.35,34.3 | 96.62,34.3 97.89,33.03 IC23.26 | 95.35,34.3 96.62,34.3 | 96.62,34.3 116.94,34.3 118.21,33.03 IC29.26 | v108.05,60.34 108.05,52.08 100.43,52.08 97.89,49.54 97.89,39.38 97.25,39.38 | 95.35,34.3 95.35,37.48 | 95.35,37.48 97.25,39.38 | 95.35,37.48 97.25,39.38
A14  (via drill 0.61)
  Top 0.254: v83.28,41.29 85.19,43.19 85.19,50.81 v95.98,50.81
  Bottom 0.254: v83.28,41.29 82.65,41.92 78.2,41.92 75.66,39.38 72.49,39.38 69.95,36.84 62.33,36.84 57.25,31.76 49.63,31.76 48.36,30.49 43.28,30.49 43.28,26.05 45.18,24.14 47.09,24.14 50.26,20.97 IC28.2 | v95.98,50.81 102.97,57.8 102.97,67.32 107.41,67.32 109.32,65.42 109.32,64.78 IC17.22
A15  (via drill 0.61)
  Top 0.254: v61.69,48.91 57.25,44.46 53.44,44.46 53.44,31.76 54.07,31.13 54.71,31.13 54.71,21.6 51.53,18.43 IC28.3 | v100.43,60.34 101.7,61.61 104.87,61.61 106.14,62.88 IC17.23
  Bottom 0.254: v61.69,48.91 62.96,50.18 84.55,50.18 86.46,52.08 90.9,52.08 99.16,60.34 v100.43,60.34 | IC29.27 118.84,36.21 115.67,39.38 115.67,43.19 114.4,43.19 113.13,44.46 113.13,52.72 109.32,56.53 109.32,61.61 108.68,61.61 107.41,62.88 IC17.23
CB1
  Top 0.254: R14.1 12.8,23.51 12.8,24.14 JP3.2
  Bottom 0.254: IC24.18 19.78,32.4 17.24,29.86 17.24,26.68 12.8,26.68 JP3.2
CDEF\  (via drill 0.61)
  Top 0.254: v101.7,21.6 101.7,20.33 99.79,18.43 IC23.20
  Bottom 0.254: IC28.10 59.79,7.63 61.06,8.9 68.04,8.9 72.49,13.35 72.49,24.14 95.35,24.14 96.62,22.87 97.89,22.87 IC23.22 100.43,22.87 v101.7,21.6
D0  (via drill 0.61)
  Top 0.254: IC22.11 64.87,12.71 76.3,12.71 77.57,11.44 80.11,11.44 81.38,12.71 82.65,12.71 IC23.11 85.19,12.71 95.35,12.71 96.62,11.44 101.7,11.44 102.97,12.71 IC29.11 | IC17.31 85.82,62.88 83.28,60.34 60.42,60.34 56.61,56.53 IC21.22 | v42.01,6.36 36.93,6.36 29.94,13.35 29.94,33.03 29.31,33.03 28.04,34.3 28.04,67.32 36.93,67.32 37.56,66.69 37.56,59.07 36.29,59.07 IC24.33
  Bottom 0.254: IC24.33 36.93,58.43 38.2,57.16 53.44,57.16 54.71,55.89 IC21.22 | v42.01,6.36 52.17,6.36 57.25,11.44 59.79,11.44 60.42,12.08 61.69,12.08 62.33,12.71 IC22.11
D1  (via drill 0.61)
  Top 0.254: v76.3,8.9 66.14,8.9 64.87,10.17 IC22.12 62.33,10.17 61.06,11.44 54.71,11.44 52.17,13.98 v43.91,13.98 | IC21.21 57.25,53.35 62.96,59.07 85.82,59.07 89,62.24 IC17.30 | v43.28,54.62 38.2,54.62 36.93,55.89 IC24.32 34.39,55.89 29.94,55.89 29.94,47 30.58,46.37 30.58,28.59 v32.48,26.68
  Bottom 0.254: v76.3,8.9 80.11,8.9 81.38,10.17 82.65,10.17 IC23.12 85.19,10.17 85.82,10.17 87.09,8.9 100.43,8.9 101.06,9.54 102.33,9.54 102.97,10.17 IC29.12 | v43.28,54.62 44.55,53.35 54.71,53.35 IC21.21 | v43.91,13.98 43.91,21.6 42.01,21.6 36.93,26.68 v32.48,26.68
D2  (via drill 0.61)
  Top 0.254: 81.38,6.36 66.14,6.36 64.87,7.63 IC22.13 | 81.38,6.36 82.65,7.63 IC23.13 | 81.38,6.36 101.7,6.36 102.97,7.63 IC29.13 | v42.64,52.08 38.2,52.08 36.93,53.35 IC24.31 34.39,53.35 30.58,53.35 30.58,47.64 31.21,47 31.21,29.22 v35.02,25.41 | v75.03,56.53 84.55,56.53 90.9,62.88 IC17.29
  Bottom 0.254: v42.64,52.08 43.91,50.81 54.71,50.81 IC21.20 56.61,51.45 69.95,51.45 v75.03,56.53 | v35.02,25.41 36.29,25.41 36.29,9.54 36.93,8.9 40.1,8.9 40.1,7 43.28,3.82 59.79,3.82 62.96,7 IC22.13
D3  (via drill 0.61)
  Top 0.254: 52.8,49.54 38.2,49.54 36.93,50.81 IC24.30 | 52.8,49.54 53.44,49.54 54.71,48.27 IC21.19 | IC17.28 94.08,62.24 97.89,58.43 109.32,58.43 115.67,64.78 118.21,64.78 120.11,62.88 120.11,50.81 121.38,50.81 122.02,50.18 122.02,47 123.92,47 125.19,45.73 125.19,7 122.65,7 120.75,5.09 IC29.15 | v52.8,54.62 52.8,49.54 | v59.15,56.53 62.33,59.7 85.19,59.7 v86.46,60.97
  Bottom 0.254: IC22.15 80.11,5.09 81.38,6.36 96.62,6.36 97.89,5.09 IC23.15 100.43,5.09 101.7,6.36 116.94,6.36 118.21,5.09 IC29.15 | v52.8,54.62 57.25,54.62 v59.15,56.53 | v86.46,60.97 87.09,61.61 92.17,61.61 93.44,62.88 IC17.28
D4  (via drill 0.61)
  Top 0.254: IC21.18 54.71,45.73 53.44,47 38.2,47 36.93,48.27 IC24.29 | v123.92,43.19 123.92,12.08 120.11,8.27 IC29.16 | v121.38,56.53 121.38,67.32 107.41,67.32 104.87,69.86 103.6,69.86 102.97,69.23 102.97,65.42 98.52,65.42 97.25,64.15 IC17.27
  Bottom 0.254: IC22.16 80.11,7.63 81.38,8.9 85.82,8.9 87.09,7.63 97.89,7.63 IC23.16 100.43,7.63 101.7,8.9 116.94,8.9 118.21,7.63 IC29.16 | IC17.27 95.98,64.15 94.71,65.42 78.2,65.42 77.57,64.78 77.57,50.81 58.52,50.81 57.25,49.54 38.2,49.54 36.93,48.27 IC24.29 | v123.92,43.19 121.38,45.73 v121.38,56.53
D5  (via drill 0.61)
  Top 0.254: IC22.17 80.11,10.17 81.38,11.44 95.35,11.44 96.62,10.17 97.89,10.17 IC23.17 | v66.14,44.46 72.49,44.46 72.49,49.54 75.66,52.72 v81.38,52.72 83.92,55.26 110.59,55.26 v111.22,55.89 | v122.65,40.65 123.29,40.65 123.29,13.98 120.11,10.81 IC29.17
  Bottom 0.254: IC29.17 118.21,10.17 116.94,11.44 101.7,11.44 100.43,10.17 IC23.17 | 53.44,44.46 54.71,43.19 IC21.17 | 53.44,44.46 36.93,44.46 36.29,45.1 IC24.28 | v81.38,52.72 88.36,52.72 98.52,62.88 IC17.26 | 53.44,44.46 v66.14,44.46 | v122.65,40.65 120.75,42.56 120.75,52.08 115.03,52.08 v111.22,55.89
D6  (via drill 0.61)
  Top 0.254: v65.5,39.38 64.23,40.65 57.25,40.65 IC21.16 54.71,40.65 54.07,40.65 54.07,32.4 54.71,31.76 55.34,31.76 55.34,20.97 v54.07,19.7 | v54.07,13.98 64.87,13.98 65.5,13.35 76.93,13.35 77.57,12.71 IC22.18
  Bottom 0.254: IC22.18 80.11,12.71 81.38,11.44 96.62,11.44 97.89,12.71 IC23.18 100.43,12.71 101.7,13.98 116.94,13.98 118.21,12.71 IC29.18 | IC24.27 36.93,43.19 38.2,41.92 50.9,41.92 52.17,40.65 54.71,40.65 IC21.16 | v65.5,39.38 69.31,39.38 73.12,43.19 85.19,43.19 85.19,49.54 85.82,50.18 90.27,50.18 97.89,57.8 101.7,57.8 101.7,62.24 IC17.25 | v54.07,13.98 v54.07,19.7
D7  (via drill 0.61)
  Top 0.254: v97.89,50.81 97.89,44.46 103.6,44.46 117.57,30.49 117.57,29.22 120.75,29.22 121.38,28.59 121.38,15.89 120.11,15.89 IC29.19 | v23.59,29.22 23.59,20.97 v24.23,20.97
  Bottom 0.254: IC21.15 54.71,38.11 53.44,39.38 38.2,39.38 36.93,40.65 IC24.26 35.02,40.02 24.23,29.22 v23.59,29.22 | IC29.19 118.21,15.25 116.94,16.52 101.7,16.52 100.43,15.25 IC23.19 97.89,15.25 96.62,13.98 81.38,13.98 80.11,15.25 IC22.19 77.57,15.25 64.87,2.55 35.02,2.55 35.02,10.17 v24.23,20.97 | v97.89,50.81 99.79,52.72 104.24,52.72 104.24,62.24 IC17.24
E  (via drill 0.61)
  Top 0.254: IC18.9 123.92,53.99 123.92,55.26 IC18.10 | v67.41,69.86 69.31,69.86 71.85,67.32 75.03,67.32 78.2,64.15 IC17.34 | v118.84,59.7 118.84,62.24 114.4,62.24 109.32,57.16 v86.46,57.16 | v76.3,45.73 77.57,47 77.57,51.45 v78.84,51.45
  Bottom 0.254: IC24.25 36.29,37.48 36.93,36.84 53.44,36.84 54.71,35.57 IC21.14 57.25,35.57 62.96,41.29 68.68,41.29 73.12,45.73 v76.3,45.73 | IC2.3 54.07,78.12 60.42,71.77 IC2.9 62.33,71.13 66.14,71.13 v67.41,69.86 | v118.84,59.7 119.48,59.7 123.29,55.89 IC18.10 | v86.46,57.16 85.82,56.53 83.92,56.53 | 83.92,56.53 78.84,61.61 78.84,62.24 IC17.34 | v78.84,51.45 83.92,56.53
EP
  Top 0.254: IC28.4 52.17,15.25 57.25,15.25 IC28.13
EP1\
  Bottom 0.254: IC28.7 51.53,8.27 56.61,13.35 56.61,17.79 57.25,17.79 IC28.14
FIRQ\  (via drill 0.61)
  Top 0.254: IC24.37 35.02,69.23 35.02,70.5 IC24.38 | R8.1 71.22,46.37 71.22,47 IC17.4 71.22,49.54 69.95,49.54 v69.95,53.99
  Bottom 0.254: v69.95,53.99 69.31,53.99 60.42,62.88 53.44,62.88 51.53,64.78 39.47,64.78 36.29,67.96 IC24.37
GND  (via drill 0.61)
  Top 0.508: IC27.7 14.07,5.09 15.34,3.82 26.13,3.82 27.4,2.55 C.2 28.04,3.19 28.04,4.46 C6.2 | 28.04,5.73 28.04,7 C4.2 28.04,8.27 28.04,9.54 C5.2 | 47.09,6.36 44.55,6.36 43.28,5.09 39.47,5.09 IC19.8 | 47.09,6.36 49.63,8.9 59.79,8.9 62.96,5.73 IC22.14 62.33,5.09 61.06,3.82 | 61.06,3.82 53.44,3.82 52.17,5.09 IC28.8 | 81.38,3.82 82.65,5.09 IC23.14 | 61.06,3.82 81.38,3.82 | 81.38,3.82 101.7,3.82 102.97,5.09 IC29.14 | 47.09,6.36 47.72,6.36 47.72,4.46 46.45,3.19 36.29,3.19 35.66,3.82 30.58,3.82 28.67,5.73 28.04,5.73 | IC26.10 8.35,27.32 9.62,26.05 JP3.1 | IC26.19 14.7,48.91 10.89,52.72 10.26,52.72 BYP26.2 10.26,53.99 8.99,55.26 8.35,55.26 IC25.10 6.45,55.89 5.81,55.89 CORE-IO.10 5.18,55.26 3.27,53.35 CORE-IO.11 | IC21.1 40.74,61.61 40.74,62.88 BYP21.2 40.74,64.15 42.64,64.15 42.64,67.32 41.37,68.59 QG1.7 | IC24.1 19.15,76.21 16.61,76.21 IC25.19 14.7,76.85 10.26,76.85 10.26,80.66 BYP25.2 | COM.5 109.95,71.77 114.4,71.77 COM.G2 118.21,74.31 122.02,78.12 C3.2 | BYP20.2 66.14,74.31 | 70.58,80.66 IC20.15 | C11.2 76.93,68.59 78.2,67.32 85.82,67.32 89.63,71.13 COM.G1 91.54,70.5 95.98,66.05 97.89,66.05 99.16,67.32 RS-232.2 | IC20.15 71.85,81.93 73.76,83.83 82.65,83.83 83.92,82.56 IC20.10 | JP1.1 116.94,48.27 116.94,50.18 IC18.7 115.67,50.81 115.03,50.81 BYP18.2 113.76,50.81 v106.78,50.81 | BYP19.2 40.74,26.05 40.74,27.32 R13.1 | BYP28.2 53.44,24.78 52.8,24.78 51.53,23.51 IC28.1 49.63,22.87 48.36,21.6 44.55,21.6 v43.28,22.87 | BYP17.2 63.6,43.83 63.6,47 IC17.1 63.6,49.54 61.06,52.08 54.71,52.08 54.07,52.72 54.07,58.43 54.71,58.43 IC21.23 | IC21.23 55.34,59.07 53.44,60.97 53.44,65.42 BYP2.2
  Top 0.508: IC17.39 65.5,62.88 63.6,60.97 59.79,60.97 57.25,58.43 IC21.23 | v52.17,41.92 v52.17,33.67 | v66.14,42.56 66.77,41.92 71.85,41.92 73.12,40.65 BYP22.2 | 70.58,80.66 66.14,76.21 62.33,76.21 IC2.11 | 70.58,80.66 IC20.15 | BYP23.2 99.79,45.73 100.43,45.73 EP-1.1 102.97,45.73 103.6,45.73 108.05,41.29 113.13,41.29 113.76,40.65 BYP29.2 114.4,40.02 114.4,34.94 115.03,34.94 118.21,31.76 120.75,31.76 122.02,30.49 122.02,13.98 116.94,13.98 v108.05,5.09 | C6.2 28.04,5.73 | C6.2 28.04,5.73
  Bottom 0.508: IC26.10 8.35,28.59 13.43,33.67 13.43,48.27 14.07,48.27 IC26.19 | BYP24.2 20.42,78.12 20.42,76.85 IC24.1 | 9.62,72.4 10.26,72.4 | 9.62,72.4 6.45,72.4 5.18,71.13 JP4.1 | 10.26,72.4 14.07,76.21 IC25.19 | 10.26,72.4 37.56,72.4 40.74,69.23 QG1.7 | 9.62,72.4 9.62,57.8 8.35,56.53 IC25.10 | 89,74.94 89.63,74.31 90.27,74.31 COM.G1 | 89,74.94 83.92,80.02 IC20.10 | 89,74.94 109.95,74.94 109.95,71.77 COM.5 | v43.28,22.87 42.64,22.87 40.74,24.78 BYP19.2 | v52.17,33.67 48.99,33.67 47.09,31.76 40.74,31.76 40.74,28.59 R13.1 | v52.17,41.92 61.69,41.92 62.96,43.19 BYP17.2 64.23,43.19 65.5,43.19 v66.14,42.56 | IC17.39 66.77,64.15 69.95,67.32 72.49,67.32 72.49,74.94 71.85,75.58 71.22,76.21 66.14,76.21 | IC21.1 42.01,60.97 43.28,62.24 57.25,62.24 57.88,61.61 57.88,59.07 56.61,59.07 IC21.23 | 5.18,7 3.91,8.27 3.91,21.6 6.45,21.6 | 5.18,7 9.62,2.55 10.89,2.55 12.16,3.82 12.16,4.46 IC27.7 | 6.45,21.6 9.62,24.78 JP3.1 | 5.18,7 C7.2 | 66.14,76.21 62.33,76.21 IC2.11 | 66.14,76.21 66.14,74.31 BYP20.2 | 6.45,21.6 15.34,21.6 15.34,24.78 BYP27.2 | v106.78,50.81 101.7,50.81 100.43,49.54 100.43,46.37 101.06,46.37 EP-1.1 | v108.05,5.09 105.51,5.09 IC29.14
HLT\
  Top 0.254: IC17.40 63.6,64.78 63.6,65.42 R5.1
IO-E\  (via drill 0.61)
  Top 0.254: v28.67,29.22 29.31,29.22 29.31,9.54 29.94,8.9 31.85,8.9 36.93,3.82 43.28,3.82 44.55,5.09 IC19.9
  Bottom 0.254: v28.67,29.22 32.48,33.03 34.39,33.03 IC24.23
IO-F\
  Top 0.254: IC19.7 37.56,8.27 36.29,9.54 36.29,26.68 36.93,26.68 38.2,27.95 38.2,34.3 42.01,34.3 42.64,34.94 42.64,40.02 41.37,40.02 IC21.9
IRQ\
  Top 0.254: R7.1 38.83,45.73 39.47,45.73 IC21.7
  Bottom 0.254: IC17.3 68.04,47.64 66.77,46.37 62.33,46.37 61.69,47 43.28,47 42.01,45.73 IC21.7
N$1
  Bottom 0.254: COM.6 100.43,73.04 101.06,72.4 106.14,72.4 106.78,71.77 COM.4
N$2
  Top 0.254: QG1.8 48.36,69.23 52.17,73.04 52.8,73.04 IC2.5
  Bottom 0.254: IC2.1 52.8,83.2 51.53,81.93 51.53,74.31 52.8,74.31 IC2.5
N$3
  Top 0.254: IC2.10 60.42,74.31 59.15,75.58 59.15,81.29 59.79,81.29 IC2.13
N$4  (via drill 0.61)
  Top 0.254: v106.14,24.14 97.25,24.14 97.25,33.67 98.52,34.94 IC23.27 | v106.78,27.95 106.78,40.02 103.6,43.19 102.97,43.19 EP-1.2
  Bottom 0.254: v106.14,24.14 106.14,27.95 v106.78,27.95
N$5
  Top 0.254: IC25.18 16.61,73.67 19.15,73.67 IC24.2
N$6
  Top 0.254: IC18.5 116.3,56.53 116.3,57.8 IC18.4 116.3,59.07 116.3,60.34 IC18.3
N$7  (via drill 0.61)
  Top 0.254: v57.88,80.66 57.88,71.77 60.42,69.23 IC2.8
  Bottom 0.254: v57.88,80.66 60.42,83.2 IC2.14
N$21
  Top 0.254: R1.1 112.49,68.59 121.38,68.59 C3.1
  Bottom 0.254: IC18.1 118.21,66.05 120.75,68.59 121.38,68.59 C3.1
N$22  (via drill 0.61)
  Top 0.254: v113.13,59.7 113.13,56.53 111.22,54.62 105.51,54.62 105.51,47 108.68,43.83 116.3,43.83 118.84,46.37 JP1.2
  Bottom 0.254: R2.1 114.4,65.42 115.03,65.42 116.3,64.15 IC18.2 115.67,63.51 113.13,63.51 v113.13,59.7
N$23  (via drill 0.61)
  Top 0.254: v24.86,22.24 v24.86,33.67 | IC21.3 42.01,55.89 43.28,55.89 44.55,54.62 44.55,53.99 43.91,53.99 43.28,53.35 42.01,53.35 IC21.4
  Bottom 0.254: v24.86,22.24 18.51,22.24 18.51,15.89 13.43,10.81 IC27.5 | v24.86,33.67 33.75,42.56 33.75,49.54 36.93,49.54 40.1,52.72 IC21.4
N$24
  Top 0.254: IC26.18 15.97,46.37 17.88,48.27 17.88,53.35 19.15,53.35 IC24.10
N$25
  Top 0.254: IC26.17 15.97,43.83 18.51,46.37 18.51,50.81 19.15,50.81 IC24.11
N$27
  Top 0.254: IC27.2 11.53,17.79 10.89,17.79 R11.A 10.26,16.52 10.26,11.44 7.72,11.44 R11.S 8.35,9.54 10.26,7.63 11.53,7.63 IC27.6
  Bottom 0.254: IC27.6 14.07,7.63 15.34,6.36 22.32,6.36 22.96,5.73 C6.1 22.96,4.46 22.96,3.19 C.1
N$28
  Top 0.254: 18.51,1.28 10.89,1.28 7.72,4.46 6.45,4.46 6.45,17.16 8.99,19.7 10.89,19.7 11.53,20.33 IC27.1 | 18.51,1.28 19.78,2.55 R10.2 | 18.51,1.28 28.67,1.28 29.94,2.55 R9.1
N$94
  Bottom 0.254: IC26.16 15.97,41.29 17.88,43.19 17.88,48.27 19.15,48.27 IC24.12
N$124
  Bottom 0.254: IC26.15 15.97,38.75 17.24,40.02 17.24,41.29 18.51,42.56 18.51,45.73 19.15,45.73 IC24.13
N$125
  Bottom 0.254: IC26.14 15.97,36.21 17.88,38.11 17.88,40.65 19.78,42.56 IC24.14
N$126
  Top 0.254: IC26.13 15.97,33.67 17.88,35.57 17.88,40.65 19.15,40.65 IC24.15
N$127
  Bottom 0.254: IC26.12 15.97,31.13 18.51,33.67 18.51,38.11 19.15,38.11 IC24.16
N$128
  Top 0.254: IC26.11 15.97,28.59 18.51,31.13 18.51,35.57 19.15,35.57 IC24.17
N$129
  Top 0.254: IC25.17 16.61,71.13 19.15,71.13 IC24.3
N$130
  Top 0.254: IC25.16 16.61,68.59 19.15,68.59 IC24.4
N$131
  Top 0.254: IC25.15 16.61,66.05 19.15,66.05 IC24.5
N$132
  Top 0.254: IC25.14 16.61,63.51 19.15,63.51 IC24.6
N$133
  Top 0.254: IC25.13 16.61,60.97 19.15,60.97 IC24.7
N$134
  Top 0.254: IC25.12 16.61,58.43 19.15,58.43 IC24.8
N$135
  Top 0.254: IC25.11 16.61,55.89 19.15,55.89 IC24.9
N$136
  Top 0.254: IC26.1 8.99,50.81 9.62,50.18 10.26,50.18 13.43,47 13.43,41.92 21.69,41.92 22.32,41.29 22.32,31.13 21.05,31.13 IC24.19
N$137
  Bottom 0.254: IC25.1 8.99,78.75 10.26,80.02 16.61,80.02 18.51,78.12 18.51,74.94 29.94,74.94 31.21,73.67 34.39,73.67 IC24.39
N$138
  Top 0.254: IC27.9 21.05,7 21.69,6.36 23.59,6.36 26.77,9.54 26.77,74.94 33.12,74.94 34.39,76.21 IC24.40
N$140
  Top 0.254: 24.86,8.9 23.59,7.63 C4.1 | 24.86,8.9 25.5,9.54 R4.1 25.5,10.81 24.86,10.81 21.05,14.62 IC27.12 | 24.86,8.9 18.51,8.9 18.51,7 19.78,5.73 IC27.8
N$141
  Top 0.254: IC27.13 21.69,17.79 22.32,17.79 R3.1 23.59,17.79 24.86,17.79 R4.2
N$142
  Bottom 0.254: IC27.11 21.69,12.71 24.23,15.25 27.4,15.25 C5.1
N$143
  Top 0.254: R10.1 12.16,2.55 10.89,3.82 10.26,3.82 R11.E
N$145
  Top 0.254: COM.7 103.6,73.67 104.87,73.67 COM.8
N$147
  Top 0.254: IC18.12 123.92,61.61 123.92,62.88 IC18.13 123.92,64.15 122.65,64.15 122.65,66.69 123.29,67.32 123.29,79.39 117.57,85.1 47.72,85.1 45.18,82.56 13.43,82.56 13.43,78.12 14.07,77.48 43.28,77.48 43.28,64.15 45.18,62.24 45.18,53.35 42.64,50.81 42.01,50.81 IC21.5
N$148
  Top 0.254: LED1.K 123.29,48.91 123.29,49.54 122.65,50.18 122.65,58.43 123.29,58.43 IC18.11
N$149
  Top 0.254: R12.1 122.02,43.83 123.29,45.1 LED1.A
N$150  (via drill 0.61)
  Top 0.254: R13.2 48.99,27.95 49.63,27.95 JP2.1 51.53,28.59 52.8,28.59 52.8,31.13 52.17,31.76 50.9,31.76 50.9,35.57 42.01,44.46 31.85,44.46 v31.85,47.64
  Bottom 0.254: v31.85,47.64 31.85,59.07 32.48,59.7 53.44,59.7 54.71,60.97 IC21.24
N$151  (via drill 0.61)
  Top 0.254: v81.38,20.33 80.11,21.6 77.57,21.6 75.66,23.51 66.14,23.51 65.5,24.14 62.33,24.14 59.15,20.97 IC28.15
  Bottom 0.254: v81.38,20.33 82.65,19.06 122.65,19.06 125.19,21.6 125.19,50.18 IC18.8
N$153
  Top 0.254: IC20.7 84.55,73.04 85.82,73.04 IC20.8
N$154
  Bottom 0.254: C7.1 5.81,12.71 8.35,15.25 11.53,15.25 IC27.3
N$155
  Top 0.254: C9.2 80.74,71.13 79.47,72.4 78.84,72.4 IC20.5
N$156
  Top 0.254: C9.1 76.3,71.77 76.3,72.4 IC20.4
N$157
  Top 0.254: C8.2 73.76,69.23 75.03,70.5 75.03,72.4 73.76,72.4 IC20.3
N$158
  Bottom 0.254: C8.1 68.68,69.23 69.95,70.5 69.95,72.4 68.68,72.4 IC20.1
N$159
  Top 0.254: C11.1 81.38,69.23 82.65,70.5 82.65,72.4 81.38,72.4 IC20.6
N$160
  Top 0.254: C10.2 73.12,71.13 71.85,72.4 71.22,72.4 IC20.2
NMI\
  Top 0.254: IC17.2 66.14,47 67.41,45.73 68.04,45.73 R6.1
PIA-A0
  Top 0.254: IC25.2 6.45,76.21 5.18,74.94 2.64,74.94 2,74.31 2,66.69 2.64,66.69 CORE-IO.1
PIA-A1
  Top 0.254: IC25.3 7.08,73.04 5.81,71.77 5.81,66.69 5.18,66.69 CORE-IO.2
PIA-A2
  Bottom 0.254: IC25.4 7.08,70.5 3.91,67.32 3.91,65.42 2.64,64.15 CORE-IO.3
PIA-A3
  Top 0.254: IC25.5 8.35,67.96 9.62,66.69 9.62,64.78 5.81,64.78 5.18,64.15 CORE-IO.4
PIA-A4
  Bottom 0.254: IC25.6 7.08,65.42 6.45,64.78 4.54,64.78 3.91,64.15 3.91,61.61 2.64,61.61 CORE-IO.5
PIA-A5
  Top 0.254: IC25.7 7.08,62.88 5.81,61.61 5.18,61.61 CORE-IO.6
PIA-A6
  Top 0.254: IC25.8 7.08,60.34 6.45,59.7 4.54,59.7 3.27,58.43 CORE-IO.7
PIA-A7
  Top 0.254: IC25.9 6.45,58.43 5.81,58.43 CORE-IO.8
PIA-B0
  Bottom 0.254: IC26.2 7.08,48.91 6.45,49.54 4.54,49.54 3.27,50.81 CORE-IO.13
PIA-B1
  Top 0.254: IC26.3 8.35,46.37 9.62,47.64 9.62,49.54 5.81,49.54 5.18,50.18 CORE-IO.14
PIA-B2
  Top 0.254: IC26.4 7.08,43.83 6.45,44.46 4.54,44.46 3.91,45.1 3.91,47.64 2.64,47.64 CORE-IO.15
PIA-B3
  Bottom 0.254: IC26.5 8.35,41.29 9.62,42.56 9.62,47 5.81,47 5.18,47.64 CORE-IO.16
PIA-B4
  Top 0.254: IC26.6 7.08,38.75 3.91,41.92 3.91,43.83 2.64,45.1 CORE-IO.17
PIA-B5
  Bottom 0.254: IC26.7 7.08,36.21 3.91,39.38 3.91,45.73 4.54,45.73 CORE-IO.18
PIA-B6
  Top 0.254: IC26.8 7.08,33.67 2.64,38.11 2.64,42.56 CORE-IO.19
PIA-B7
  Top 0.254: IC26.9 8.35,31.13 9.62,32.4 9.62,41.92 5.81,41.92 5.18,42.56 CORE-IO.20
Q  (via drill 0.61)
  Top 0.254: v56.61,71.77 v56.61,76.85
  Bottom 0.254: v56.61,71.77 54.07,69.23 IC2.7 | 57.25,77.48 58.52,78.75 59.79,78.75 IC2.12 | v56.61,76.85 57.25,77.48 | 57.25,77.48 80.11,77.48 80.11,68.59 76.3,64.78 IC17.35
R/W\  (via drill 0.61)
  Top 0.254: 69.31,36.84 61.06,36.84 57.25,33.03 IC21.13 | 69.31,36.84 76.3,36.84 77.57,35.57 IC22.27 | v83.92,57.8 72.49,57.8 64.87,50.18 64.87,41.29 69.31,36.84
  Bottom 0.254: IC24.21 36.93,27.95 38.2,26.68 41.37,26.68 42.64,27.95 42.64,31.13 47.72,31.13 48.99,32.4 55.34,32.4 IC21.13 | v83.92,57.8 83.92,62.24 IC17.32
RST\  (via drill 0.61)
  Top 0.254: v110.59,60.97 108.68,59.07 98.52,59.07 95.35,62.24 95.35,65.42 80.74,65.42 80.11,64.78 80.11,61.61 73.12,61.61 71.85,62.88 IC17.37
  Bottom 0.254: IC24.34 36.29,61.61 37.56,62.88 37.56,64.78 34.39,64.78 33.75,65.42 33.75,69.86 36.93,69.86 41.37,65.42 52.17,65.42 54.07,63.51 61.06,63.51 62.96,61.61 69.31,61.61 70.58,62.88 IC17.37 | v110.59,60.97 110.59,57.8 113.76,54.62 114.4,54.62 115.67,53.35 IC18.6
RX  (via drill 0.61)
  Top 0.254: v41.37,66.69 38.83,66.69 38.83,60.34 40.1,59.07 IC21.2 | v63.6,69.86 66.14,72.4 66.77,72.4 67.41,73.04 67.41,76.21 73.76,76.21 78.2,80.66 IC20.12
  Bottom 0.254: v41.37,66.69 42.01,67.32 57.25,67.32 59.79,69.86 v63.6,69.86
RXD
  Top 0.254: 96.62,72.4 93.44,75.58 82.65,75.58 82.65,82.56 82.01,83.2 78.2,83.2 76.93,81.93 IC20.13 | 96.62,72.4 96.62,69.86 RS-232.3 | 96.62,72.4 102.33,72.4 103.6,71.13 COM.3
TX  (via drill 0.61)
  Top 0.254: v33.75,52.08 33.75,50.18 34.39,49.54 36.93,49.54 37.56,48.91 38.83,48.91 39.47,48.27 IC21.6 | v75.03,75.58 78.84,79.39 79.47,79.39 80.74,80.66 IC20.11
  Bottom 0.254: v33.75,52.08 33.75,54.62 42.01,54.62 44.55,52.08 69.31,52.08 75.03,57.8 v75.03,75.58
TXD
  Top 0.254: COM.2 101.7,70.5 101.7,69.86 RS-232.1
  Bottom 0.254: IC20.14 74.39,80.66 76.93,78.12 84.55,78.12 88.36,74.31 88.36,66.69 101.06,66.69 101.7,67.32 RS-232.1
VCC  (via drill 0.61)
  Top 0.508: IC24.24 36.29,36.21 37.56,37.48 38.2,37.48 R7.2 | IC21.10 39.47,38.11 38.83,38.11 R7.2 | IC21.8 40.1,42.56 38.2,40.65 38.2,38.75 R7.2 | IC28.16 58.52,23.51 58.52,24.78 BYP28.1 | IC19.16 45.82,23.51 45.82,24.78 BYP19.1 45.82,26.05 45.82,33.03 | 45.82,33.03 42.01,33.03 IC21.12 | 45.82,33.03 47.09,33.03 49.63,30.49 JP2.2 | IC24.20 20.42,27.32 20.42,26.05 BYP27.1 20.42,24.78 20.42,20.97 IC27.14 | R14.2 5.81,22.87 7.08,21.6 14.7,21.6 17.88,21.6 19.15,20.33 IC27.14 | IC27.4 14.07,12.71 16.61,10.17 19.15,10.17 IC27.10 21.69,10.17 22.32,10.17 R3.2 | IC27.4 13.43,13.35 | IC29.1 102.97,38.11 100.43,38.11 IC23.28 | IC17.7 78.84,47 78.84,46.37 R8.2 78.84,45.1 78.84,43.19 | IC22.28 78.84,38.75 78.84,40.02 BYP22.1 78.84,41.29 78.84,43.19 | 78.84,43.19 69.31,43.19 BYP17.1 | IC23.28 97.89,38.11 85.19,38.11 IC23.1 | R12.2 122.02,36.21 120.75,37.48 120.11,37.48 IC29.28 119.48,38.75 119.48,40.02 BYP29.1 119.48,41.29 119.48,44.46 120.11,44.46 120.75,45.1 120.75,50.18 119.48,50.18 118.84,50.81 118.84,54.62 115.03,54.62 114.4,55.26 BYP18.1 113.76,55.89 v110.59,52.72 | R2.2 106.14,66.05 104.24,67.96 R1.2 | 50.26,82.56 51.53,81.29 52.17,81.29 IC2.2 54.07,80.66 55.34,79.39 55.34,76.85 54.07,76.85 IC2.4 54.07,75.58 55.34,74.31 55.34,71.77 54.07,71.77 IC2.6 | 50.26,82.56 48.99,83.83 QG1.14 47.72,83.83 42.64,78.75 26.13,78.75 BYP24.1 24.86,78.75 22.32,81.29 15.97,81.29 BYP25.1 15.34,80.66 15.34,79.39 IC25.20 | 50.26,82.56 67.41,82.56 68.04,81.93 IC20.16 | BYP20.1 66.14,69.23 66.14,71.13 68.04,71.13 C10.1 | R5.2 70.58,66.05 69.31,67.32 68.04,67.32 66.77,68.59 BYP20.1 | BYP21.1 45.82,64.15 52.17,70.5 52.8,70.5 IC2.6
  Top 0.508: 57.88,67.32 54.71,70.5 54.07,70.5 IC2.6 | 57.88,67.32 58.52,66.69 BYP2.1 | 57.88,67.32 64.23,67.32 65.5,68.59 BYP20.1 | IC26.20 15.34,51.45 15.34,52.72 BYP26.1 | 13.43,13.35 19.78,19.7 IC27.14 | IC27.4 13.43,13.35 | EP-1.3 100.43,40.65 99.79,40.65 BYP23.1 99.16,40.02 99.16,38.75 IC23.28
  Bottom 0.508: 38.83,32.4 39.47,33.03 IC21.12 | 38.83,32.4 36.93,30.49 IC24.22 34.39,30.49 31.85,27.95 21.69,27.95 IC24.20 | IC28.16 57.25,22.87 55.98,24.14 48.36,24.14 47.09,25.41 46.45,25.41 BYP19.1 | 38.83,32.4 36.29,34.94 IC24.24 | R3.2 23.59,10.17 24.86,8.9 30.58,8.9 30.58,9.54 R9.2 | R6.2 61.69,45.73 66.77,45.73 68.68,43.83 BYP17.1 | IC23.1 82.65,38.11 80.11,38.11 IC22.28 | BYP18.1 114.4,56.53 114.4,62.24 119.48,62.24 123.29,66.05 IC18.14 123.92,66.69 123.92,68.59 122.65,69.86 121.38,69.86 120.75,69.23 115.03,69.23 114.4,69.86 111.22,69.86 | 111.22,69.86 106.14,69.86 104.87,68.59 R1.2 | 3.27,54.62 2.64,55.26 CORE-IO.9 2.64,56.53 1.37,57.8 1.37,73.67 2.64,73.67 JP4.2 4.54,74.31 4.54,77.48 12.8,77.48 14.07,78.75 IC25.20 | 3.27,54.62 4.54,53.35 CORE-IO.12 | 3.27,54.62 13.43,54.62 14.7,53.35 BYP26.1 | 111.22,69.86 111.22,83.2 70.58,83.2 69.31,81.93 IC20.16 | v110.59,52.72 110.59,47 108.68,45.1 104.87,45.1 104.87,38.75 IC29.1 | R14.2 5.18,23.51 5.18,34.3 8.99,34.3 12.16,37.48 12.16,50.81 14.07,50.81 IC26.20

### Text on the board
Top: Component Side
Bottom: PA8PDP/VRS | Solder side
tPlace: 1 | F09 | 2,54 | 6 | 9 | 1 | 5 | 1 | + | 1 | 1 | 20 | 1 | 3 | 1 | 2 | 3 | RealConsole CORE - Rev.1
tNames: IC2 | QG1 | IC25 | BYP25 | IC24 | BYP24 | IC20 | C9 | JP4 | C8 | BYP20 | C3 | R5 | RS-232 | R1 | IC18 | COM | R2 | IC21 | BYP18 | IC26 | BYP26 | IC17 | LED1 | R8 | R7 | R6 | BYP17 | R12 | IC23 | BYP23 | IC22 | BYP22 | BYP29 | R13 | IC19 | IC28 | BYP27 | R14 | IC27 | R3 | R4 | R10 | R9
tValues: .01uf | 4Mhz | 74LS73N | .01uf | 74LS245N | MAX232 | + | 22uf | POWER | 6821 | 10K | - | .01uf | 0.1uf | 10K | 0.1uf | 3.3K | 74LS132N | 6850 | .01uf | .01uf | 6809E | 74LS245N | 3.3K | .01uf | 3.3K | 3.3K | LO/27256 | .01uf | .01uf | HI/27128 | 270 | .01uf | 6264A | 27C128P | .01uf | 1K | 3.3K | 74LS138N | 74LS139N | LM556N | 100K | 100K | 3.3K | 10K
